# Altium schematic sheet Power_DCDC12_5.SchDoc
size A4
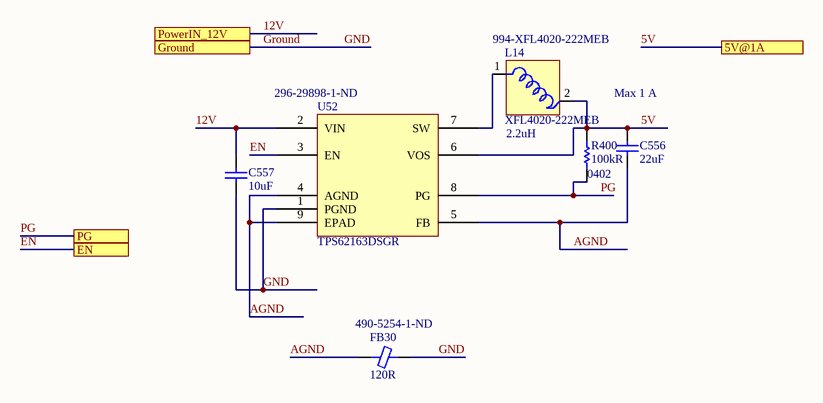
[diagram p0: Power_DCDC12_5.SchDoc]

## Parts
C556  22uF  [CAP 0603/1608 RF]
C557  10uF  [CAP 0805/2012 RF]
FB30  120R  Supplier Part Number 1: 490-5254-1-ND  [FER 0603/1608]
L14  XFL4020-222MEB  Inductance: 2.2uH  Supplier Part Number 1: 994-XFL4020-222MEB  [XFL4020 Series]
R400  100kR  Case/Package: 0402  [RES 0402/1005 RF]
U52  TPS62163DSGR  Supplier Part Number 1: 296-29898-1-ND  [TPS62163]

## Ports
5V@1A, EN, Ground, PG, PowerIN_12V

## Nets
5V: C556.2 L14.2 R400.2 U52.6(VOS) ; port 5V@1A
12V: C557.2 U52.2(VIN) ; port PowerIN_12V
AGND: C556.1 FB30.1 U52.4(AGND) U52.5(FB) U52.9(EPAD)
EN: U52.3(EN) ; port EN
GND: C557.1 FB30.2 U52.1(PGND) ; port Ground  [also labelled Ground]
PG: R400.1 U52.8(PG) ; port PG
NetL14_1: L14.1 U52.7(SW)

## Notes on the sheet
- Max 1 A

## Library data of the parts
C556 = Capacitor: 0603 22 uF 10 V ±20% Tolerance X5R Multilayer Ceramic Chip Capacitor; Manufacturer: Murata; Manufacturer Part Number: GRM188R61A226ME15D; Voltage Rating: 10V
C557 = Capacitor: Manufacturer 1: Samsung; Manufacturer Part Number 1: CL21A106KOQNNNG; Material: Ceramic; Tolerance: 10%; Dielectric: X5R; Voltage: 16V
FB30 = Ferrite: MURATA - BLM18KG121TN1D - Ferritperle, 0603 [Metrisch 1608], 120 ohm, 3 A, Baureihe EMIFIL BLM18K, 0.03 ohm, ± 25%; Material: Ferrite,Steel; Current Rating: 3A; Number of Lines: 1; DC Resistance (DCR): 30mR; Test Frequency: 100MHz
L14 = XFL4020-222MEB: Power inductor, shielded, 20% tol, SMT, RoHS, halogen free; Manufacturer: Coilcraft; Core Material: Composite; Self Resonant Frequency: 38MHz; Max DC Current: 8A; DC Resistance (DCR): 23.5mR; Test Frequency: 100kHz
R400 = Resistor: Manufacturer 1: Panasonic; Manufacturer Part Number 1: ERA-2AED104X; Tolerance: 0.5%; Power Rating: 63mW; Voltage Rating: 25V; Temperature Coefficient: 25ppm/°C
U52 = TPS62163DSGR: IC REG BUCK 5V 1A SYNC 8WSON; Manufacturer 1: Texas Instruments; Switching Frequency: 2.25MHz; Number of Outputs: 1; Max Input Voltage: 17V; Min Input Voltage: 3V; Synchronous Rectifier: Yes; Quiescent Current: 17uA; Output Type: Fixed; Output Configuration: Positive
